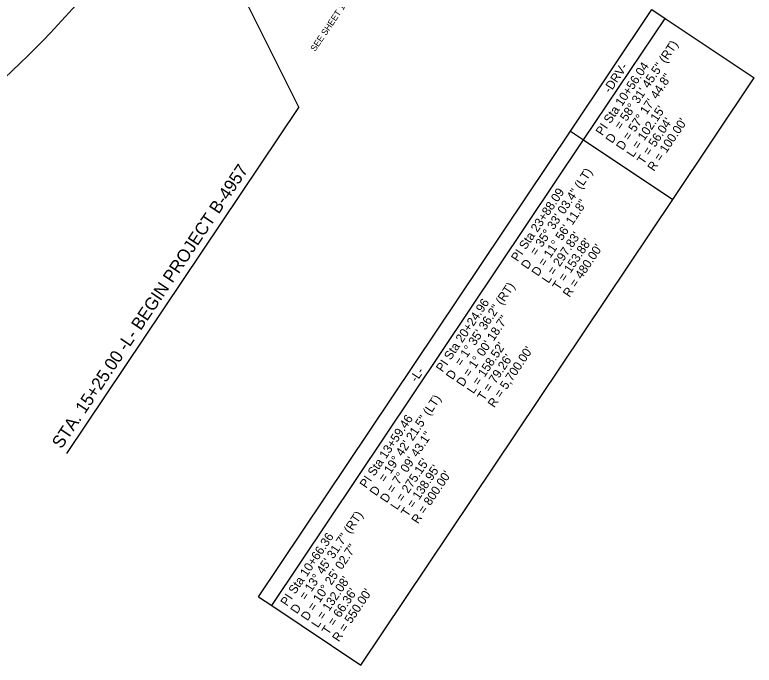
# Model space of a CAD drawing. Extents: x 1716813 to 1718091, y 800228 to 801730.
# Drawn here: x 1717290 to 1717878, y 800228 to 800746 of the extents above; entities that cross this region are included whole.
import ezdxf

# ---------------------------------------------------------------- set-up
doc = ezdxf.new("R2010")
doc.units = 0
for name, color, linetype in [('Prop Dimension', 7, 'Continuous'), ('Prop DSN Text', 7, 'Continuous'), ('Prop Horizontal Alignment', 7, 'Continuous'), ('Prop Horizontal Alignment Curve and Spiral Data', 7, 'Continuous')]:
    doc.layers.add(name, color=color, linetype=linetype)

msp = doc.modelspace()

# ---------------------------------------------------------------- linework, layer by layer
at = {"layer": 'Prop Dimension'}
for p in [(1717420.81, 800862.88), (1717331.6, 800396.46)]:
    msp.add_line(p, (1717515.94, 800671.88), dxfattribs=at)
at = {"layer": 'Prop Horizontal Alignment'}
msp.add_arc((1716739.67, 801283.48), 800, 306.49907, 326.20506, dxfattribs=at)
at = {"layer": 'Prop Horizontal Alignment Curve and Spiral Data'}
for p, q in [((1717732, 800653.05), (1717796.76, 800749.8)), ((1717796.76, 800749.8), (1717807.29, 800742.75)), ((1717742.54, 800646), (1717807.29, 800742.75)), ((1717807.29, 800742.75), (1717878.19, 800695.29)), ((1717813.44, 800598.55), (1717878.19, 800695.29)), ((1717483.97, 800282.47), (1717732, 800653.05)), ((1717732, 800653.05), (1717742.54, 800646)), ((1717494.5, 800275.42), (1717742.54, 800646)), ((1717742.54, 800646), (1717813.44, 800598.55)), ((1717565.4, 800227.97), (1717813.44, 800598.55)), ((1717483.97, 800282.47), (1717494.5, 800275.42)), ((1717494.5, 800275.42), (1717565.4, 800227.97))]:
    msp.add_line(p, q, dxfattribs=at)

# ---------------------------------------------------------------- texts
at = {"layer": 'Prop Dimension'}
msp.add_text('STA. 15+25.00 -L- BEGIN PROJECT B-4957', height=10, rotation=56.20506, dxfattribs=at).set_placement((1717327.21, 800399.59))
at = {"layer": 'Prop DSN Text'}
msp.add_text('SEE SHEET 1-C', height=5, rotation=56.20506, dxfattribs=at).set_placement((1717529.09, 800716.02))
at = {"layer": 'Prop Horizontal Alignment Curve and Spiral Data'}
for s, p in [('= 58%%d 31\' 45.5" (RT)', (1717772.18, 800653.63)), ('PI Sta 10+56.04', (1717757.34, 800648.91)), ('-DRV-', (1717763.5, 800682.7)), ('D = 57%%d 17\' 44.8"', (1717773.59, 800637.22)), ("L = 102.15'", (1717781.9, 800631.66)), ("T = 56.04'", (1717790.21, 800626.1)), ("R = 100.00'", (1717798.52, 800620.53)), ('D', (1717765.28, 800642.78)), ('= 35%%d 33\' 03.4" (LT)', (1717704.91, 800553.37)), ('PI Sta 23+88.09', (1717690.07, 800548.65)), ('D = 11%%d 56\' 11.8"', (1717706.31, 800536.96)), ("L = 297.83'", (1717714.62, 800531.4)), ("T = 153.88'", (1717722.93, 800525.84)), ("R = 480.00'", (1717731.24, 800520.27)), ('D', (1717698, 800542.52)), ('= 1%%d 35\' 36.2" (RT)', (1717645.17, 800465.46)), ('PI Sta 20+24.96', (1717630.34, 800460.74)), ('D = 1%%d 00\' 18.7"', (1717646.58, 800449.05)), ("L = 158.52'", (1717654.89, 800443.49)), ("R = 5,700.00'", (1717671.51, 800432.37)), ("T = 79.26'", (1717663.2, 800437.93)), ('-L-', (1717609.55, 800452.59)), ('D', (1717638.27, 800454.61)), ('= 19%%d 42\' 21.5" (LT)', (1717584.48, 800373.04)), ('PI Sta 13+59.46', (1717569.64, 800368.32)), ('D = 7%%d 09\' 43.1"', (1717585.89, 800356.63)), ("L = 275.15'", (1717594.2, 800351.07)), ("T = 138.95'", (1717602.51, 800345.51)), ("R = 800.00'", (1717610.82, 800339.95)), ('D', (1717577.58, 800362.19)), ('= 13%%d 45\' 31.7" (RT)', (1717521.49, 800279.17)), ('PI Sta 10+66.36', (1717506.65, 800274.45)), ('D = 10%%d 25\' 02.7"', (1717522.89, 800262.77)), ("L = 132.08'", (1717531.21, 800257.2)), ("T = 66.36'", (1717539.52, 800251.64)), ("R = 550.00'", (1717547.83, 800246.08)), ('D', (1717514.58, 800268.33))]:
    msp.add_text(s, height=7, rotation=56.20506, dxfattribs=at).set_placement(p)

doc.saveas('drawing.dxf')
